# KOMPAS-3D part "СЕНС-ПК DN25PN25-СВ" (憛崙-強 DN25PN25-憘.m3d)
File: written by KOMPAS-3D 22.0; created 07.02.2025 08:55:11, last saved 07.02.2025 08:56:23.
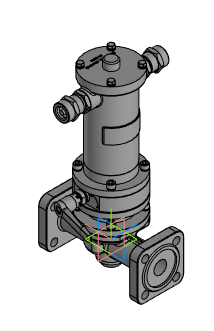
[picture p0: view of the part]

Document properties: Автор: setup; Полное имя файла: \\10.10.77.77\!! users\Савин А.Г\!Клапаны 3D для заказчика\СЕНС-ПК\1. СЕНС-ПК\СЕНС-ПК DN25PN25-СВ.m3d

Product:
- Body: Тело 3
    Масса: 10.63044
- Part/product: СЕНС-ПК DN25PN25-СВ
    Масса: 10.456296

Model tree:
1. Операция без истории:1
2. Эскиз:1  (with: Операция без истории:1)
3. Элемент выдавливания:1
     Расстояние 1 = 14
4. Фаска:1  (with: Элемент выдавливания:1)  (labels: 9Ā9␣8␣8Ā9␣8Ā9␣8␣8␣8␣8␣8␣8␣8␣8␣8␣8␣8␣8␣8␣8␣8␣8␣8␣8␣8␣8␣8␣)
     Угол = 45; Длина 1 = 2; Длина 2 = 2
